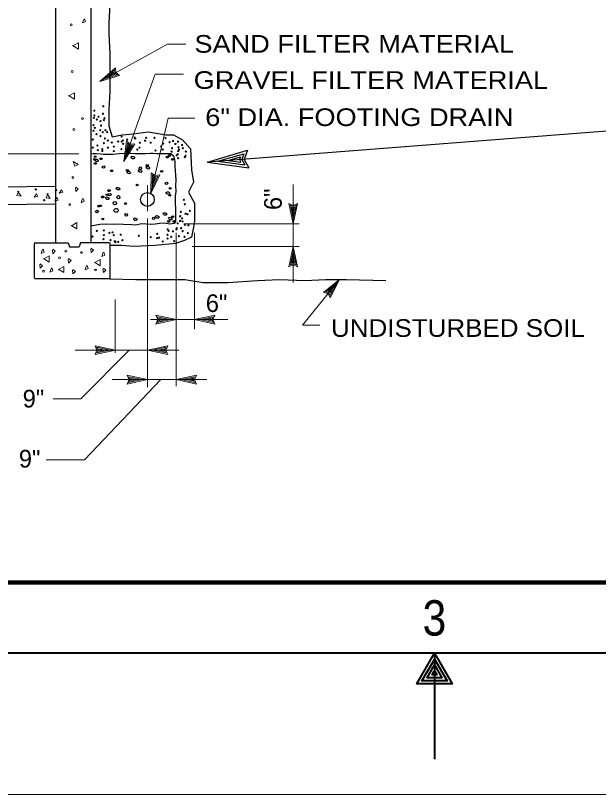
# Model space of a CAD drawing. Extents: x -22.3 to 19.7, y -11.8 to 18.2.
# Drawn here: x -4.28 to -0.15, y -11.84 to -6.32 of the extents above; entities that cross this region are included whole.
import ezdxf
from ezdxf.enums import TextEntityAlignment as Align

# ---------------------------------------------------------------- set-up
doc = ezdxf.new("R2010")
doc.units = 0
doc.header["$LTSCALE"] = 0.05
doc.layers.add('1', color=7, linetype='Continuous', lineweight=13)
doc.layers.add('2', color=7, linetype='Continuous', lineweight=13)

msp = doc.modelspace()

# ---------------------------------------------------------------- linework, layer by layer
at = {"layer": '1', "lineweight": 25}
for p, q in [((-3.99142, -7.93169), (-3.99142, -3.95369)), ((-3.74142, -7.93169), (-3.74142, -4.32169)), ((-2.84242, -7.35669), (-2.65842, -7.30269)), ((-2.77042, -7.35169), (-2.68242, -7.32469)), ((-2.68242, -7.32469), (-2.68942, -7.34469)), ((-2.65842, -7.30269), (-2.67342, -7.34369)), ((-2.91642, -7.36269), (-2.62442, -7.40269)), ((-2.84242, -7.35669), (-2.65242, -7.38269)), ((-2.77042, -7.35169), (-2.67942, -7.36269)), ((-2.68942, -7.34469), (-2.67942, -7.36269)), ((-2.67342, -7.34369), (-2.65242, -7.38269)), ((-10.87842, -7.59969), (-3.99142, -7.53369)), ((-10.88242, -7.72469), (-3.99142, -7.65869)), ((-4.14542, -7.93369), (-3.90442, -7.93369)), ((-4.14242, -8.18269), (-4.14242, -7.94069)), ((-3.90442, -7.93369), (-3.89442, -7.96169)), ((-3.81542, -7.93069), (-3.82642, -7.96169)), ((-3.81542, -7.93069), (-3.61142, -7.93069)), ((-3.60542, -8.18969), (-3.60542, -7.93369)), ((-3.89442, -7.96169), (-3.82642, -7.96169)), ((-4.14242, -8.18569), (-3.60742, -8.18569))]:
    msp.add_line(p, q, dxfattribs=at)
at = {"layer": '1'}
for p, q in [((-3.19942, -6.52669), (-3.07042, -6.52669)), ((-3.64842, -6.77269), (-3.57542, -6.70969)), ((-3.61642, -6.75569), (-3.58142, -6.72469)), ((-3.58142, -6.72469), (-3.58042, -6.73569)), ((-3.57542, -6.70969), (-3.57342, -6.73169)), ((-3.68042, -6.79069), (-3.53942, -6.74869)), ((-3.64842, -6.77269), (-3.55642, -6.74569)), ((-3.61642, -6.75569), (-3.57242, -6.74169)), ((-3.58042, -6.73569), (-3.57242, -6.74169)), ((-3.57342, -6.73169), (-3.55642, -6.74569)), ((-3.51042, -7.35769), (-3.28842, -6.74069)), ((-3.28842, -6.74069), (-3.08642, -6.74069)), ((-3.31742, -7.58469), (-3.19542, -7.05069)), ((-3.19542, -7.05069), (-3.00742, -7.05069)), ((-3.51042, -7.35769), (-3.49042, -7.21169)), ((-3.51042, -7.35769), (-3.43242, -7.23269)), ((-3.49742, -7.32269), (-3.48442, -7.22769)), ((-3.49742, -7.32269), (-3.44742, -7.24169)), ((-3.48542, -7.28869), (-3.47942, -7.24369)), ((-3.48542, -7.28869), (-3.46242, -7.24969)), ((-3.48442, -7.22769), (-3.46942, -7.24269)), ((-3.47942, -7.24369), (-3.47142, -7.25069)), ((-3.47142, -7.25069), (-3.46242, -7.24969)), ((-3.46942, -7.24269), (-3.44742, -7.24169)), ((-3.82742, -7.30469), (-5.89942, -7.30469)), ((-3.31742, -7.58469), (-3.31542, -7.43769)), ((-3.31742, -7.58469), (-3.25542, -7.45169)), ((-3.30942, -7.54869), (-3.30742, -7.45269)), ((-3.30942, -7.54869), (-3.26842, -7.46169)), ((-3.30742, -7.45269), (-3.29042, -7.46569)), ((-3.30142, -7.51369), (-3.30042, -7.46769)), ((-3.30142, -7.51369), (-3.28242, -7.47169)), ((-3.30042, -7.46769), (-3.29242, -7.47369)), ((-3.29242, -7.47369), (-3.28242, -7.47169)), ((-3.29042, -7.46569), (-3.26842, -7.46169)), ((-3.34242, -7.52669), (-3.34242, -7.70869)), ((-2.30942, -7.79869), (-2.34042, -7.65469)), ((-2.30942, -7.79869), (-2.27842, -7.65469)), ((-2.30942, -7.76169), (-2.32942, -7.66769)), ((-2.32942, -7.66769), (-2.30942, -7.67669)), ((-2.30942, -7.72569), (-2.31942, -7.68069)), ((-2.31942, -7.68069), (-2.30942, -7.68469)), ((-2.30942, -7.76169), (-2.28942, -7.66769)), ((-2.30942, -7.67669), (-2.28942, -7.66769)), ((-2.30942, -7.72569), (-2.30042, -7.68069)), ((-2.30942, -7.68469), (-2.30042, -7.68069)), ((-3.34242, -7.76269), (-3.34242, -8.95669)), ((-3.08542, -7.79869), (-2.26742, -7.79869)), ((-3.13942, -7.86369), (-3.13942, -8.94969)), ((-3.00942, -7.86369), (-3.00942, -8.54569)), ((-3.02642, -7.96069), (-2.26742, -7.96069)), ((-2.30942, -7.95969), (-2.34042, -8.10369)), ((-2.30942, -7.99669), (-2.32942, -8.09069)), ((-2.30942, -7.95969), (-2.27842, -8.10369)), ((-2.30942, -7.99669), (-2.28942, -8.09069)), ((-2.30942, -8.03269), (-2.31842, -8.07769)), ((-2.30942, -8.03269), (-2.29942, -8.07769)), ((-2.30942, -8.08169), (-2.32942, -8.09069)), ((-2.30942, -8.07369), (-2.31842, -8.07769)), ((-2.29942, -8.07769), (-2.30942, -8.07369)), ((-2.28942, -8.09069), (-2.30942, -8.08169)), ((-1.98042, -8.19269), (-2.09542, -8.28469)), ((-2.00342, -8.22169), (-2.07842, -8.28169)), ((-2.02642, -8.24969), (-2.06142, -8.27869)), ((-2.00342, -8.22169), (-2.04742, -8.30669)), ((-2.02642, -8.24969), (-2.04742, -8.29069)), ((-2.05742, -8.28769), (-2.07842, -8.28169)), ((-2.05242, -8.28069), (-2.06142, -8.27869)), ((-2.04742, -8.30669), (-2.05742, -8.28769)), ((-2.04742, -8.29069), (-2.05242, -8.28069)), ((-3.57142, -8.33569), (-3.57142, -8.71369)), ((-3.13942, -8.47769), (-3.28342, -8.44669)), ((-3.13942, -8.47769), (-3.28342, -8.50869)), ((-3.17642, -8.47769), (-3.27042, -8.45769)), ((-3.26142, -8.47769), (-3.27042, -8.45769)), ((-3.17642, -8.47769), (-3.27042, -8.49769)), ((-3.27042, -8.49769), (-3.26142, -8.47769)), ((-3.21242, -8.47769), (-3.25742, -8.46869)), ((-3.25342, -8.47769), (-3.25742, -8.46869)), ((-3.21242, -8.47769), (-3.25742, -8.48769)), ((-3.25742, -8.48769), (-3.25342, -8.47769)), ((-3.00842, -8.47769), (-2.86442, -8.44669)), ((-3.00842, -8.47769), (-2.86442, -8.50869)), ((-2.97142, -8.47769), (-2.87742, -8.45769)), ((-2.97142, -8.47769), (-2.87742, -8.49769)), ((-2.93542, -8.47769), (-2.89042, -8.46769)), ((-2.93542, -8.47769), (-2.89042, -8.48669)), ((-2.89042, -8.46769), (-2.89442, -8.47769)), ((-2.89442, -8.47769), (-2.89042, -8.48669)), ((-2.87742, -8.45769), (-2.88642, -8.47769)), ((-2.88642, -8.47769), (-2.87742, -8.49769)), ((-2.24442, -8.51769), (-2.12142, -8.51769)), ((-3.47042, -8.69369), (-3.81442, -9.03769)), ((-3.56942, -8.69369), (-3.71342, -8.66269)), ((-3.56942, -8.69369), (-3.71342, -8.72469)), ((-3.60642, -8.69369), (-3.70042, -8.67369)), ((-3.69142, -8.69369), (-3.70042, -8.67369)), ((-3.60642, -8.69369), (-3.70042, -8.71369)), ((-3.70042, -8.71369), (-3.69142, -8.69369)), ((-3.64242, -8.69369), (-3.68742, -8.68469)), ((-3.68342, -8.69369), (-3.68742, -8.68469)), ((-3.64242, -8.69369), (-3.68742, -8.70369)), ((-3.68742, -8.70369), (-3.68342, -8.69369)), ((-3.34242, -8.69369), (-3.19842, -8.66269)), ((-3.34242, -8.69369), (-3.19842, -8.72469)), ((-3.30542, -8.69369), (-3.21142, -8.67369)), ((-3.30542, -8.69369), (-3.21142, -8.71369)), ((-3.26942, -8.69369), (-3.22442, -8.68369)), ((-3.26942, -8.69369), (-3.22442, -8.70269)), ((-3.22442, -8.68369), (-3.22842, -8.69369)), ((-3.22842, -8.69369), (-3.22442, -8.70269)), ((-3.21142, -8.67369), (-3.22042, -8.69369)), ((-3.22042, -8.69369), (-3.21142, -8.71369)), ((-3.34242, -8.90269), (-3.48642, -8.87169)), ((-3.13942, -8.90269), (-2.99542, -8.87169)), ((-3.24742, -8.90269), (-3.78742, -9.46969)), ((-3.34242, -8.90269), (-3.48642, -8.93369)), ((-3.37942, -8.90269), (-3.47342, -8.88269)), ((-3.46442, -8.90269), (-3.47342, -8.88269)), ((-3.37942, -8.90269), (-3.47342, -8.92269)), ((-3.47342, -8.92269), (-3.46442, -8.90269)), ((-3.41542, -8.90269), (-3.46042, -8.89369)), ((-3.45642, -8.90269), (-3.46042, -8.89369)), ((-3.41542, -8.90269), (-3.46042, -8.91269)), ((-3.46042, -8.91269), (-3.45642, -8.90269)), ((-3.13942, -8.90269), (-2.99542, -8.93369)), ((-3.10242, -8.90269), (-3.00842, -8.88269)), ((-3.10242, -8.90269), (-3.00842, -8.92269)), ((-3.06642, -8.90269), (-3.02142, -8.89269)), ((-3.06642, -8.90269), (-3.02142, -8.91169)), ((-3.02142, -8.89269), (-3.02542, -8.90269)), ((-3.02542, -8.90269), (-3.02142, -8.91169)), ((-3.00842, -8.88269), (-3.01742, -8.90269)), ((-3.01742, -8.90269), (-3.00842, -8.92269)), ((-3.81442, -9.03769), (-4.00942, -9.03769)), ((-3.78742, -9.46969), (-4.05942, -9.46969)), ((19.69058, -11.83969), (-22.30942, -11.83969))]:
    msp.add_line(p, q, dxfattribs=at)
at = {"layer": '1', "lineweight": 40}
msp.add_line((-1.30942, -10.83969), (-1.30942, -11.58969), dxfattribs=at)
for points in [[(-21.30942, -10.83969), (-21.30942, 17.16031), (18.69058, 17.16031), (18.69058, -10.83969)], [(-1.30942, -10.83969), (-1.18442, -11.05669), (-1.43442, -11.05669)]]:
    msp.add_lwpolyline(points, close=True, dxfattribs=at)
at = {"layer": '1', "lineweight": 90}
msp.add_lwpolyline([(-19.80942, 16.66031), (18.19058, 16.66031), (18.19058, -10.33969), (-19.80942, -10.33969)], close=True, dxfattribs=at)
at = {"layer": '1', "lineweight": 25}
for points in [[(-3.60742, -6.24369), (-3.61442, -6.37869), (-3.61442, -6.45669), (-3.60742, -6.59269), (-3.60742, -6.65669), (-3.60742, -6.86269), (-3.61442, -6.99069), (-3.61442, -7.10469), (-3.59242, -7.18369), (-3.52142, -7.16869), (-3.44342, -7.16169), (-3.33642, -7.14769), (-3.20842, -7.16869), (-3.15842, -7.16869), (-3.09442, -7.20469), (-3.03742, -7.26869), (-3.03042, -7.41769), (-3.01642, -7.50369), (-3.05142, -7.57469), (-3.00942, -7.65269), (-3.00942, -7.78069), (-3.01642, -7.82369), (-3.03042, -7.89469), (-3.08042, -7.91669), (-3.14442, -7.93769), (-3.28642, -7.95169), (-3.43642, -7.95869), (-3.52842, -7.95169), (-3.60742, -7.95169)], [(0.39758, -7.10569), (-2.91642, -7.36269), (-2.63442, -7.27869)], [(-2.63442, -7.27869), (-2.65742, -7.34269), (-2.62442, -7.40269)], [(-3.74142, -7.30469), (-3.72542, -7.30069), (-3.70342, -7.30169), (-3.67142, -7.30469), (-3.65242, -7.30569), (-3.61642, -7.30569), (-3.58742, -7.30569), (-3.54242, -7.30169), (-3.50042, -7.29969), (-3.46042, -7.29969), (-3.42842, -7.30069), (-3.38542, -7.30069), (-3.35542, -7.30169), (-3.32042, -7.29869), (-3.30042, -7.29969), (-3.27742, -7.30069), (-3.25042, -7.30069), (-3.21242, -7.30169), (-3.17742, -7.30069), (-3.15842, -7.31669), (-3.14842, -7.35669), (-3.14742, -7.38769), (-3.14242, -7.45369), (-3.14042, -7.49069), (-3.14242, -7.52769), (-3.14142, -7.57069), (-3.14542, -7.60269), (-3.14542, -7.64669), (-3.14342, -7.69969), (-3.14242, -7.71669), (-3.14342, -7.78169), (-3.15342, -7.79769), (-3.18342, -7.80069), (-3.22042, -7.79469), (-3.25342, -7.79769), (-3.28642, -7.80269), (-3.31442, -7.80369), (-3.35042, -7.80069), (-3.38142, -7.79869), (-3.42742, -7.80969), (-3.45342, -7.80669), (-3.51142, -7.80469), (-3.54942, -7.80269), (-3.58242, -7.80369), (-3.63942, -7.80069), (-3.67942, -7.80369), (-3.74242, -7.81569)], [(-3.60542, -8.18969), (-3.42342, -8.19269), (-3.31442, -8.19269), (-3.17942, -8.19269), (-3.07742, -8.19269), (-2.94842, -8.21369), (-2.77242, -8.21369), (-2.56242, -8.19969), (-2.40642, -8.19269), (-2.22442, -8.19969), (-2.08142, -8.19269), (-1.93242, -8.19269), (-1.65442, -8.19969)]]:
    msp.add_lwpolyline(points, dxfattribs=at)
at = {"layer": '1'}
for points in [[(-3.19942, -6.52669), (-3.68042, -6.79069), (-3.56942, -6.69469)], [(-3.56942, -6.69469), (-3.56642, -6.72769), (-3.53942, -6.74869)], [(-3.49042, -7.21169), (-3.46642, -7.23569), (-3.43242, -7.23269)], [(-3.31542, -7.43769), (-3.28842, -7.45769), (-3.25542, -7.45169)], [(-2.30942, -8.21469), (-2.30942, -7.95969), (-2.30942, -7.79869), (-2.30942, -7.51969)], [(-2.34042, -7.65469), (-2.30942, -7.66869), (-2.27842, -7.65469)], [(-2.27842, -8.10369), (-2.30942, -8.08969), (-2.34042, -8.10369)], [(-2.24442, -8.51769), (-1.98042, -8.19269), (-2.04742, -8.32369)], [(-2.04742, -8.32369), (-2.06242, -8.29369), (-2.09542, -8.28469)], [(-3.32142, -8.47769), (-3.13942, -8.47769), (-3.00842, -8.47769), (-2.77242, -8.47769)], [(-3.28342, -8.50869), (-3.26942, -8.47769), (-3.28342, -8.44669)], [(-2.86442, -8.44669), (-2.87842, -8.47769), (-2.86442, -8.50869)], [(-3.85442, -8.69369), (-3.56942, -8.69369), (-3.34242, -8.69369), (-3.11942, -8.69369)], [(-3.71342, -8.72469), (-3.69942, -8.69369), (-3.71342, -8.66269)], [(-3.19842, -8.66269), (-3.21242, -8.69369), (-3.19842, -8.72469)], [(-3.48642, -8.93369), (-3.47242, -8.90269), (-3.48642, -8.87169)], [(-2.99542, -8.87169), (-3.00942, -8.90269), (-2.99542, -8.93369)], [(-3.59142, -8.90269), (-3.34242, -8.90269), (-3.13942, -8.90269), (-2.92242, -8.90269)]]:
    msp.add_lwpolyline(points, dxfattribs=at)
at = {"layer": '1', "lineweight": 40}
for points in [[(-1.30842, -10.88269), (-1.21942, -11.03569), (-1.39742, -11.03569), (-1.30942, -10.88369)], [(-1.30942, -10.92169), (-1.25642, -11.01469), (-1.36142, -11.01469), (-1.30742, -10.92169)], [(-1.30942, -10.96469), (-1.29242, -10.99369), (-1.32542, -10.99369), (-1.31042, -10.96769)]]:
    msp.add_lwpolyline(points, dxfattribs=at)
at = {"layer": '1'}
for centre in [(-3.71792, -6.99769), (-3.65492, -6.96669), (-3.72192, -7.04869), (-3.71792, -7.03269), (-3.69992, -7.06069), (-3.68892, -7.04069), (-3.65692, -7.01969), (-3.64692, -7.05069), (-3.72392, -7.10069), (-3.67492, -7.07269), (-3.67092, -7.10369), (-3.65092, -7.06569), (-3.72392, -7.13969), (-3.71492, -7.12069), (-3.70292, -7.16369), (-3.67592, -7.13569), (-3.65892, -7.15069), (-3.63992, -7.13569), (-3.62692, -7.14969), (-3.72892, -7.20269), (-3.67492, -7.17869), (-3.64992, -7.22769), (-3.64292, -7.19469), (-3.62292, -7.20969), (-3.59492, -7.22369), (-3.54892, -7.21669), (-3.52492, -7.18069), (-3.52492, -7.21769), (-3.51592, -7.20969), (-3.48592, -7.20269), (-3.43292, -7.18769), (-3.42792, -7.19469), (-3.39592, -7.22469), (-3.35892, -7.21069), (-3.35092, -7.18969), (-3.31892, -7.22469), (-3.29192, -7.18969), (-3.21392, -7.19269), (-3.18492, -7.22069), (-3.16092, -7.21269), (-3.12592, -7.21769), (-3.72892, -7.25969), (-3.69692, -7.24469), (-3.69392, -7.27769), (-3.66192, -7.27069), (-3.66192, -7.28369), (-3.62192, -7.25969), (-3.57992, -7.25269), (-3.57992, -7.28369), (-3.52692, -7.27069), (-3.51392, -7.23369), (-3.41392, -7.27369), (-3.39792, -7.25969), (-3.28492, -7.27969), (-3.24592, -7.25169), (-3.23392, -7.27369), (-3.23092, -7.23169), (-3.16792, -7.26369), (-3.14392, -7.23369), (-3.12492, -7.28369), (-3.12192, -7.25669), (-3.11892, -7.27369), (-3.09692, -7.24169), (-3.09092, -7.26369), (-3.17092, -7.28769), (-3.13492, -7.31469), (-3.12792, -7.30569), (-3.12492, -7.33369), (-3.07692, -7.32669), (-3.07292, -7.31669), (-3.06992, -7.28769), (-3.08392, -7.62969), (-3.07692, -7.66069), (-3.10492, -7.71469), (-3.04092, -7.70769), (-3.11092, -7.74569), (-3.11092, -7.77869), (-3.09692, -7.76069), (-3.07192, -7.72769), (-3.05792, -7.73169), (-3.13492, -7.83069), (-3.12792, -7.79569), (-3.10392, -7.83069), (-3.09392, -7.78169), (-3.07692, -7.80569), (-3.05192, -7.80969), (-3.73092, -7.88969), (-3.69992, -7.84869), (-3.65092, -7.84569), (-3.65092, -7.87969), (-3.61192, -7.86269), (-3.58992, -7.85969), (-3.58092, -7.87969), (-3.53192, -7.87569), (-3.40292, -7.88369), (-3.27392, -7.86969), (-3.19992, -7.87669), (-3.19892, -7.83869), (-3.19192, -7.84869), (-3.17392, -7.89069), (-3.16092, -7.85269), (-3.13692, -7.83869), (-3.11892, -7.88669), (-3.09292, -7.85069), (-3.07992, -7.89069), (-3.05492, -7.86569), (-3.65392, -7.90769), (-3.60392, -7.91469), (-3.57392, -7.92269), (-3.56892, -7.92869), (-3.54892, -7.92669), (-3.51992, -7.91569), (-3.31892, -7.89369), (-3.27292, -7.90069), (-3.25992, -7.89769), (-3.23392, -7.92469), (-3.19892, -7.90369), (-3.15292, -7.92169)]:
    msp.add_circle(centre, 0.0043, dxfattribs=at)
at = {"layer": '1', "lineweight": 25}
msp.add_circle((-3.34242, -7.62669), 0.04879, dxfattribs=at)
for centre, major_axis, ratio in [((-3.71192, -7.32369), (0.0075, 0), 0.801784), ((-3.67092, -7.33869), (0.0075, 0), 0.801784), ((-3.44542, -7.32969), (0.012, -0.005), 0.691328), ((-3.20092, -7.32669), (0.0075, 0), 0.801784), ((-3.18592, -7.31569), (0.0075, 0), 0.801784), ((-3.71692, -7.34369), (0.0075, 0), 0.801784), ((-3.71092, -7.37169), (0.0075, 0), 0.801784), ((-3.70242, -7.34969), (0.012, -0.005), 0.691328), ((-3.65292, -7.39719), (0.00702, 0.00594), 0.925744), ((-3.34292, -7.38569), (0.0075, 0), 0.801784), ((-3.16492, -7.34369), (0.0075, 0), 0.801784), ((-3.59592, -7.42369), (0.0075, 0), 0.801784), ((-3.48492, -7.42069), (0.0075, 0), 0.801784), ((-3.47442, -7.43569), (0.012, -0.005), 0.691328), ((-3.39442, -7.42569), (0.012, -0.005), 0.691328), ((-3.39292, -7.40519), (0.00702, 0.00594), 0.925744), ((-3.33842, -7.40169), (0.012, -0.005), 0.691328), ((-3.24092, -7.42769), (0.0075, 0), 0.801784), ((-3.55042, -7.54969), (0.013, -0.003), 0.637098), ((-3.41492, -7.52469), (0.0075, 0), 0.801784), ((-3.20692, -7.51219), (0.00702, 0.00594), 0.925744), ((-3.18092, -7.54769), (0.0075, 0), 0.801784), ((-3.65942, -7.60969), (0.009, 0.003), 0.73994), ((-3.62542, -7.61769), (0.012, -0.005), 0.691328), ((-3.62892, -7.59269), (0.0075, 0), 0.801784), ((-3.61392, -7.56419), (0.0095, 0.0025), 0.642337), ((-3.60892, -7.59319), (0.00702, 0.00594), 0.925744), ((-3.54842, -7.61119), (0.00165, 0.01211), 0.908016), ((-3.19742, -7.58169), (0.012, -0.005), 0.691328), ((-3.18392, -7.59769), (0.0075, 0), 0.801784), ((-3.68142, -7.67269), (0.014, 0.002), 0.441415), ((-3.57292, -7.65369), (0.0115, -0.002), 0.985988), ((-3.49792, -7.65569), (0.0075, 0), 0.801784), ((-3.69942, -7.71219), (0.009, 0.0055), 0.849448), ((-3.56442, -7.70419), (0.015, 0.0015), 0.895325), ((-3.21842, -7.72969), (0.012, -0.005), 0.691328), ((-3.65792, -7.76469), (0.0075, 0), 0.801784), ((-3.49292, -7.73519), (0.00702, 0.00594), 0.925744), ((-3.42742, -7.76669), (0.012, -0.005), 0.691328), ((-3.29792, -7.76019), (0.00702, 0.00594), 0.925744), ((-3.27242, -7.75069), (0.012, -0.005), 0.691328), ((-3.18042, -7.76269), (0.012, -0.005), 0.691328), ((-3.16292, -7.74869), (0.0075, 0), 0.801784), ((-3.19192, -7.78269), (0.0075, 0), 0.801784), ((-3.15492, -7.78269), (0.0075, 0), 0.801784)]:
    msp.add_ellipse(centre, major_axis=major_axis, ratio=ratio, dxfattribs=at)
at = {"layer": '2'}
for points in [[(-3.78742, -6.34669), (-3.78042, -6.36669), (-3.80142, -6.37669), (-3.79142, -6.34669)], [(-3.86542, -6.53769), (-3.83142, -6.51769), (-3.83142, -6.56169), (-3.87242, -6.53769)], [(-3.89342, -6.89169), (-3.85942, -6.87169), (-3.85942, -6.91569), (-3.90042, -6.89169)], [(-3.84942, -7.53869), (-3.83242, -7.55269), (-3.84942, -7.56969), (-3.85242, -7.54269)], [(-4.25342, -7.56869), (-4.26742, -7.59869), (-4.23742, -7.60269), (-4.26142, -7.56869)], [(-4.04642, -7.58569), (-4.06042, -7.61569), (-4.03042, -7.61969), (-4.05442, -7.58569)], [(-3.79842, -7.61969), (-3.79142, -7.63969), (-3.81242, -7.64969), (-3.80242, -7.61969)], [(-3.87642, -7.81069), (-3.84242, -7.79069), (-3.84242, -7.83469), (-3.88342, -7.81069)], [(-4.08142, -7.97969), (-4.07442, -7.99969), (-4.09542, -8.00969), (-4.08542, -7.97969)], [(-4.01242, -7.97969), (-3.99542, -7.99369), (-4.01242, -8.01069), (-4.01542, -7.98369)], [(-3.74042, -7.97069), (-3.72342, -7.98469), (-3.74042, -8.00169), (-3.74342, -7.97469)], [(-4.07142, -8.04569), (-4.03742, -8.02569), (-4.03742, -8.06969), (-4.07842, -8.04569)], [(-3.90042, -8.04569), (-3.88342, -8.05969), (-3.90042, -8.07669), (-3.90342, -8.04969)], [(-3.71042, -8.07169), (-3.67642, -8.05169), (-3.67642, -8.09569), (-3.71742, -8.07169)], [(-3.65142, -8.00069), (-3.64442, -8.02069), (-3.66542, -8.03069), (-3.65542, -8.00069)], [(-4.10142, -8.08269), (-4.08442, -8.09669), (-4.10142, -8.11369), (-4.10442, -8.08669)], [(-3.96842, -8.12069), (-3.93442, -8.10069), (-3.93442, -8.14469), (-3.97542, -8.12069)], [(-3.76942, -8.09469), (-3.76242, -8.11469), (-3.78342, -8.12469), (-3.77342, -8.09469)], [(-4.01842, -8.11169), (-4.01142, -8.13169), (-4.03242, -8.14169), (-4.02242, -8.11169)], [(-3.86942, -8.12269), (-3.85242, -8.13669), (-3.86942, -8.15369), (-3.87242, -8.12669)], [(-3.65442, -8.11369), (-3.63742, -8.12769), (-3.65442, -8.14469), (-3.65742, -8.11769)]]:
    msp.add_lwpolyline(points, dxfattribs=at)
for points in [[(-3.86742, -7.35869), (-3.83342, -7.37869), (-3.85742, -7.39069)], [(-4.14342, -7.61069), (-4.12742, -7.58669), (-4.11942, -7.60469)], [(-3.96642, -7.58169), (-3.95042, -7.55769), (-3.94242, -7.57569)], [(-3.99742, -7.63669), (-3.98142, -7.61269), (-3.97342, -7.63069)]]:
    msp.add_lwpolyline(points, close=True, dxfattribs=at)
for centre, radius in [((-3.88192, -6.39019), 0.0065), ((-3.87492, -6.72019), 0.0065), ((-3.80192, -7.05419), 0.0065), ((-3.86292, -7.13119), 0.0065), ((-3.86992, -7.47119), 0.0065), ((-4.13292, -7.55531), 0.00487), ((-3.98992, -7.56031), 0.00487), ((-4.07292, -7.63231), 0.00487), ((-3.89292, -7.66319), 0.0065), ((-3.91992, -7.99319), 0.0065), ((-3.80992, -8.00319), 0.0065), ((-3.96492, -8.04019), 0.0065), ((-4.07892, -8.13519), 0.0065), ((-3.70992, -8.12619), 0.0065)]:
    msp.add_circle(centre, radius, dxfattribs=at)

# ---------------------------------------------------------------- texts
at = {"layer": '1'}
for s, width, p in [('SAND FILTER MATERIAL', 1.15, (-3.00942, -6.58769)), ('GRAVEL FILTER MATERIAL', 1.15, (-3.01442, -6.84369)), ('6" DIA. FOOTING DRAIN', 1.15, (-2.93242, -7.10669)), ('UNDISTURBED SOIL', 1.1, (-2.04142, -8.59969))]:
    msp.add_text(s, height=0.125, dxfattribs=dict(at, width=width)).set_placement(p)
msp.add_text('6"', height=0.125, rotation=90, dxfattribs=at).set_placement((-2.39042, -7.70169))
msp.add_text('6"', height=0.125, dxfattribs=at).set_placement((-2.92842, -8.42369))
for p in [(-4.07342, -9.09969), (-4.10042, -9.52469)]:
    msp.add_text('9"', height=0.125, dxfattribs=at).set_placement(p, align=Align.RIGHT)
at = {"layer": '1', "width": 0.9}
msp.add_text('3', height=0.25, dxfattribs=at).set_placement((-1.30892, -10.71469), align=Align.CENTER)

doc.saveas('drawing.dxf')
